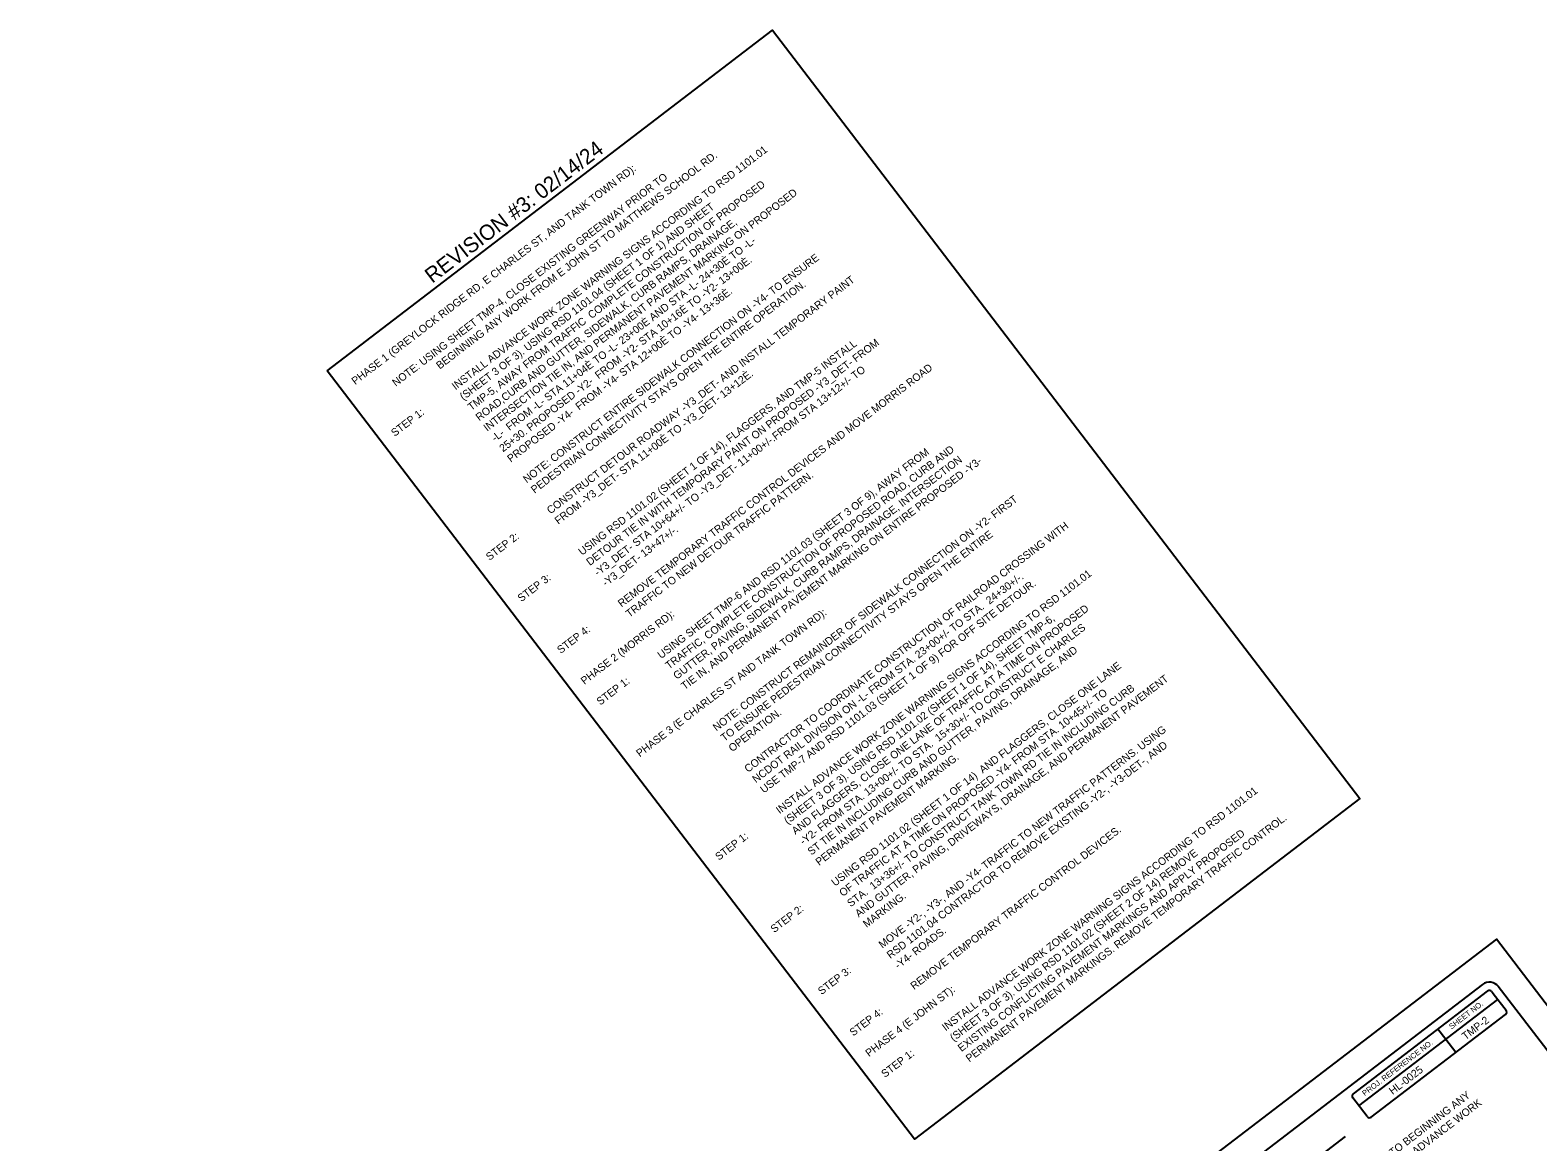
# Model space of a CAD drawing. Extents: x -606 to 2396, y -305 to 3662.
# Drawn here: x -5 to 1374, y 1764 to 2781 of the extents above; entities that cross this region are included whole.
import ezdxf

# ---------------------------------------------------------------- set-up
doc = ezdxf.new("R2010")
doc.units = 0
for name, color, linetype in [('DEV BORDER CELL', 7, 'Continuous'), ('DEV TRANSPORTATION OPERATIONS PLAN SHEET', 7, 'Continuous'), ('Scratch_Level_6', 7, 'Continuous'), ('Sheet Plot Border Outside CELL', 7, 'Continuous'), ('Text', 7, 'Continuous')]:
    doc.layers.add(name, color=color, linetype=linetype)

msp = doc.modelspace()

# ---------------------------------------------------------------- linework, layer by layer
at = {"layer": 'DEV BORDER CELL'}
for p, q in [((1323.5, 1908.3), (148.3, 1009.6)), ((1963.2, 1088.6), (1337.9, 1906.4)), ((1205.4, 1808.5), (1328.1, 1902.3)), ((1210.5, 1797.3), (1337.6, 1894.5)), ((1332, 1901.8), (1333.3, 1900.1)), ((1333.3, 1900.1), (1345, 1884.8)), ((1221.8, 1787.1), (1344.5, 1880.9)), ((1289.9, 1858), (1282.6, 1867.6)), ((1299, 1846.1), (1289.9, 1858)), ((1217.9, 1787.6), (1204.8, 1804.7)), ((1020.1, 1633.3), (1198.1, 1769.4))]:
    msp.add_line(p, q, dxfattribs=at)
for centre, radius, start, end in [((1329.8, 1900.1), 10.3, 37.404, 127.4035), ((1329.8, 1900.1), 2.79, 37.404, 127.4035), ((1342.8, 1883.1), 2.79, 307.4044, 37.4039), ((1207.1, 1806.3), 2.79, 127.4044, 218.5684), ((1220.1, 1789.3), 2.79, 217.404, 307.4044)]:
    msp.add_arc(centre, radius, start, end, dxfattribs=at)
at = {"layer": 'Scratch_Level_6'}
msp.add_lwpolyline([(266.9, 2469.3), (674.2, 2780.8), (1211.3, 2078.4), (804, 1767)], close=True, dxfattribs=at)
at = {"layer": 'Sheet Plot Border Outside CELL'}
msp.add_lwpolyline([(663.6, 50.4), (2004.5, 1075.8), (1336.4, 1949.6), (-4.5, 924.2)], close=True, dxfattribs=at)

# ---------------------------------------------------------------- texts
at = {"layer": 'DEV BORDER CELL'}
for s, height, rotation, p in [('SHEET NO.', 5, 37.4045, (1295.1, 1867.1)), ('PROJ. REFERENCE NO.', 4.999, 37.4045, (1215.8, 1806.1)), ('HL-0025         ', 7, 37.404, (1241.3, 1807.2))]:
    msp.add_text(s, height=height, rotation=rotation, dxfattribs=at).set_placement(p)
at = {"layer": 'DEV TRANSPORTATION OPERATIONS PLAN SHEET'}
msp.add_text('TMP-2   ', height=7, rotation=37.404, dxfattribs=at).set_placement((1307.9, 1857.2))
at = {"layer": 'Scratch_Level_6'}
msp.add_text('REVISION #3: 02/14/24', height=14, rotation=37.404, dxfattribs=at).set_placement((363.1, 2548.8))
at = {"layer": 'Text'}
for s, p in [('BEGINNING ANY WORK FROM E JOHN ST TO MATTHEWS SCHOOL RD. ', (370, 2470.4)), ('INSTALL ADVANCE WORK ZONE WARNING SIGNS ACCORDING TO RSD 1101.01 ', (384.4, 2451.5)), ('PHASE 1 (GREYLOCK RIDGE RD, E CHARLES ST, AND TANK TOWN RD):', (292.7, 2456.2)), ('           NOTE: USING SHEET TMP-4, CLOSE EXISTING GREENWAY PRIOR TO ', (307.1, 2437.3)), ('TMP-5, AWAY FROM TRAFFIC  COMPLETE CONSTRUCTION OF PROPOSED ', (398.9, 2432.5)), ('INTERSECTION TIE IN, AND PERMANENT PAVEMENT MARKING ON PROPOSED ', (413.3, 2413.6)), ('(SHEET 3 OF 3). USING RSD 1101.04 (SHEET 1 OF 1) AND SHEET ', (391.6, 2442)), ('ROAD,CURB AND GUTTER, SIDEWALK, CURB RAMPS, DRAINAGE, ', (406.1, 2423.1)), ('-L-  FROM -L- STA 11+04È TO -L- 23+00È AND STA -L- 24+30È TO -L- ', (420.6, 2404.2)), ('25+30. PROPOSED -Y2-  FROM -Y2- STA 10+16È TO -Y2- 13+00È. ', (427.8, 2394.7)), ('NOTE: CONSTRUCT ENTIRE SIDEWALK CONNECTION ON -Y4- TO ENSURE ', (449.5, 2366.4)), ('PEDESTRIAN CONNECTIVITY STAYS OPEN THE ENTIRE OPERATION.', (456.7, 2356.9)), ('CONSTRUCT DETOUR ROADWAY -Y3_DET- AND INSTALL TEMPORARY PAINT ', (471.2, 2338)), ('PROPOSED -Y4-  FROM -Y4- STA 12+00È TO -Y4- 13+36È. ', (435, 2385.3)), ('USING RSD 1101.02 (SHEET 1 OF 14), FLAGGERS, AND TMP-5 INSTALL ', (500.1, 2300.2)), ('DETOUR TIE IN WITH TEMPORARY PAINT ON PROPOSED -Y3_DET- FROM ', (507.3, 2290.8)), ('FROM -Y3_DET- STA 11+00È TO -Y3_DET- 13+12È. ', (478.4, 2328.6)), ('-Y3_DET- STA 10+64+/- TO -Y3_DET- 11+00+/-.FROM STA 13+12+/- TO ', (514.5, 2281.3)), ('REMOVE TEMPORARY TRAFFIC CONTROL DEVICES AND MOVE MORRIS ROAD ', (536.2, 2252.9)), ('STEP 1:', (328.8, 2408.9)), ('USING SHEET TMP-6 AND RSD 1101.03 (SHEET 3 OF 9), AWAY FROM ', (572.4, 2205.7)), ('TRAFFIC, COMPLETE CONSTRUCTION OF PROPOSED ROAD, CURB AND ', (579.6, 2196.2)), ('GUTTER, PAVING, SIDEWALK, CURB RAMPS, DRAINAGE, INTERSECTION ', (586.8, 2186.8)), ('TIE IN, AND PERMANENT PAVEMENT MARKING ON ENTIRE PROPOSED -Y3-', (594, 2177.3)), ('TRAFFIC TO NEW DETOUR TRAFFIC PATTERN.', (543.4, 2243.5)), ('NOTE: CONSTRUCT REMAINDER OF SIDEWALK CONNECTION ON -Y2- FIRST ', (623, 2139.5)), ('CONTRACTOR TO COORDINATE CONSTRUCTION OF RAILROAD CROSSING WITH ', (651.9, 2101.7)), ('STEP 2:', (415.5, 2295.5)), ('-Y3_DET- 13+47+/-.', (521.8, 2271.8)), ('TO ENSURE PEDESTRIAN CONNECTIVITY STAYS OPEN THE ENTIRE ', (630.2, 2130.1)), ('STEP 3:', (444.5, 2257.7)), ('NCDOT RAIL DIVISION ON -L- FROM STA. 23+00+/- TO STA.  24+30+/-. ', (659.1, 2092.2)), ('USE TMP-7 AND RSD 1101.03 (SHEET 1 OF 9) FOR OFF SITE DETOUR.', (666.3, 2082.8)), ('INSTALL ADVANCE WORK ZONE WARNING SIGNS ACCORDING TO RSD 1101.01 ', (680.8, 2063.9)), ('PHASE 2 (MORRIS RD):', (502.3, 2182.1)), ('PHASE 3 (E CHARLES ST AND TANK TOWN RD):', (552.9, 2115.9)), ('AND FLAGGERS, CLOSE ONE LANE OF TRAFFIC AT A TIME ON PROPOSED ', (695.2, 2045)), ('STEP 4:', (480.6, 2210.4)), ('(SHEET 3 OF 3). USING RSD 1101.02 (SHEET 1 OF 14), SHEET TMP-6, ', (688, 2054.4)), ('-Y2- FROM STA. 13+00+/- TO STA.  15+30+/- TO CONSTRUCT E CHARLES  ', (702.5, 2035.5)), ('ST TIE IN INCLUDING CURB AND GUTTER, PAVING, DRAINAGE, AND ', (709.7, 2026.1)), ('USING RSD 1101.02 (SHEET 1 OF 14)  AND FLAGGERS, CLOSE ONE LANE ', (731.4, 1997.7)), ('STEP 1:', (516.7, 2163.2)), ('STA.  13+36+/- TO CONSTRUCT TANK TOWN RD TIE IN INCLUDING CURB ', (745.8, 1978.8)), ('AND GUTTER, PAVING, DRIVEWAYS, DRAINAGE, AND PERMANENT PAVEMENT ', (753.1, 1969.4)), ('OF TRAFFIC AT A TIME ON PROPOSED -Y4- FROM STA. 10+45+/- TO ', (738.6, 1988.3)), ('OPERATION.', (637.4, 2120.6)), ('MOVE -Y2-, -Y3-, AND -Y4- TRAFFIC TO NEW TRAFFIC PATTERNS. USING ', (774.7, 1941)), ('RSD 1101.04 CONTRACTOR TO REMOVE EXISTING -Y2-, -Y3-DET-, AND ', (782, 1931.5)), ('PERMANENT PAVEMENT MARKING. ', (716.9, 2016.6)), ('INSTALL ADVANCE WORK ZONE WARNING SIGNS ACCORDING TO RSD 1101.01 ', (832.6, 1865.4)), ('PERMANENT PAVEMENT MARKINGS. REMOVE TEMPORARY TRAFFIC CONTROL.', (854.3, 1837)), ('STEP 1:', (625.2, 2021.4)), ('REMOVE TEMPORARY TRAFFIC CONTROL DEVICES.', (803.7, 1903.2)), ('EXISTING CONFLICTING PAVEMENT MARKINGS AND APPLY PROPOSED ', (847, 1846.5)), ('(SHEET 3 OF 3). USING RSD 1101.02 (SHEET 2 OF 14) REMOVE ', (839.8, 1855.9)), ('MARKING. ', (760.3, 1959.9)), ('STEP 2:', (675.8, 1955.2)), ('-Y4- ROADS.', (789.2, 1922.1)), ('STEP 3: ', (719.1, 1898.5)), ('PHASE 4 (E JOHN ST):', (762.5, 1841.8)), ('STEP 4:', (748.1, 1860.7)), ('STEP 1:', (777, 1822.8)), ('USING SHEET TMP-4, CLOSE EXISTING GREENWAY PRIOR TO BEGINNING ANY ', (1027.5, 1587.4)), ('WORK FROM E JOHN ST TO MATTHEWS SCHOOL RD. INSTALL ADVANCE WORK ', (1034.7, 1578))]:
    msp.add_text(s, height=7, rotation=37.404, dxfattribs=at).set_placement(p)

doc.saveas('drawing.dxf')
